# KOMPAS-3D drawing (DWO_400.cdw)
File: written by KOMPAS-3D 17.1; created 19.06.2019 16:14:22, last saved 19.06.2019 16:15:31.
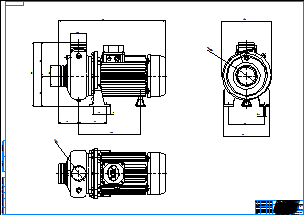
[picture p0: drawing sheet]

Sheet 1: A0, landscape

Title block, sheet 1: name: DWO_400; material: Внимание! Данный продукт является объектом авторского права ООО «Торговый Дом АДЛ». / Запрещается изменение, копирование, распространение / (в том числе путем копирования на другие сайты и ресурсы в Интернете) / или любое иное использование информации и объектов без предварительного / согласия правообладателя (ООО «Торговый Дом АДЛ»).; scale: 1:1; sheets: 1; organisation: ООО "Торговый дом АДЛ"; sheet format: A0; stored path: \\adlc.lan\data\АДЛ_ПКД\3D-модели\Поставщики\Насосное оборудование EBARA\DWO\KOMPAS 2D\DWO_400.cdw

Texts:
  user
  CONTINUOUS_RGB_0_0_0_THICK_0.18
  POLYLINE_STYLE_0.18_RGB_0_0_0
Dimensions and other numbers on the sheet: 15; 107; 78; 240.5; 415; 62.5; 80; 120; 133; 253; 50; 9; 140; 180; 193; 72; 57; 1:1; 1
